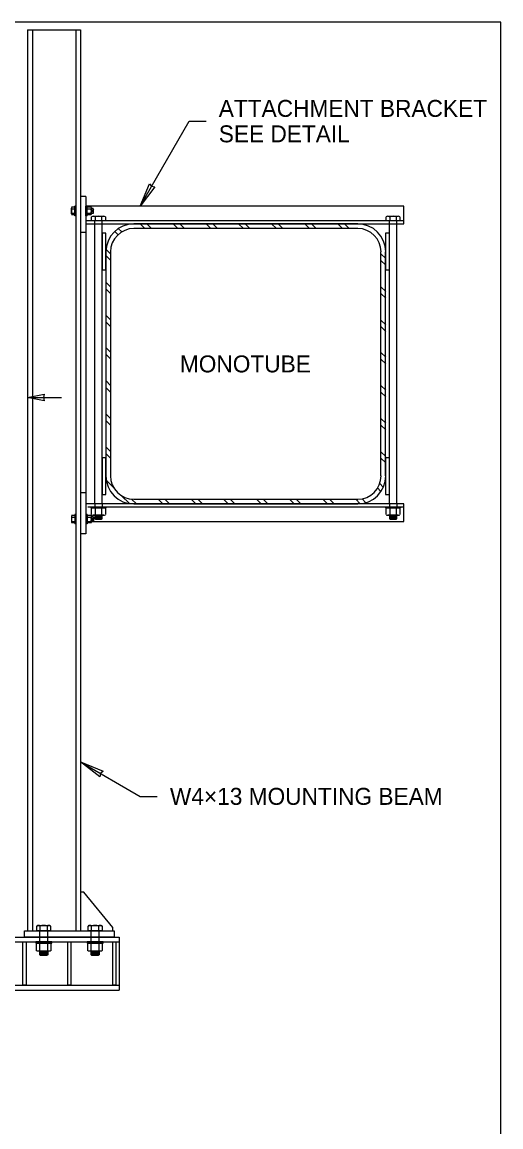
# Model space of a CAD drawing. Extents: x 99862 to 103151, y 100000 to 108076.
# Drawn here: x 102699 to 103151, y 107033 to 108076 of the extents above; entities that cross this region are included whole.
import ezdxf

# ---------------------------------------------------------------- set-up
doc = ezdxf.new("R2010")
doc.units = 0
for name, color, linetype in [('Level 1', 7, 'Continuous'), ('Level 13', 7, 'Continuous'), ('Level 15', 7, 'Continuous'), ('Level 2', 7, 'Continuous'), ('Level 20', 7, 'Continuous'), ('Level 3', 7, 'Continuous'), ('Level 30', 7, 'Continuous'), ('Level 36', 7, 'Continuous'), ('Level 4', 7, 'Continuous'), ('Level 60', 7, 'Continuous')]:
    doc.layers.add(name, color=color, linetype=linetype)

msp = doc.modelspace()

# ---------------------------------------------------------------- linework, layer by layer
at = {"layer": 'Level 1'}
msp.add_lwpolyline([(99862, 105999.5), (103151, 105999.5), (103151, 108075.5), (99862, 108075.5)], close=True, dxfattribs=at)
at = {"layer": 'Level 13'}
for p, q in [((102757.3, 107254.8), (102754.3, 107254.8)), ((102754.3, 107254.8), (102754.3, 107218.5)), ((102784.6, 107221.5), (102757.3, 107254.8)), ((102784.6, 107218.5), (102784.6, 107221.5)), ((102754.3, 107218.5), (102784.6, 107218.5)), ((102790.7, 107212.4), (102790.7, 107162.4))]:
    msp.add_line(p, q, dxfattribs=at)
msp.add_lwpolyline([(102701.3, 107218.5), (102786.1, 107218.5), (102786.1, 107212.4), (102701.3, 107212.4)], close=True, dxfattribs=at)
at = {"layer": 'Level 15'}
for p, q in [((102810.4, 107901.9), (102856.7, 107982.1)), ((102856.7, 107982.1), (102872.7, 107982.1)), ((102704.3, 107721.5), (102736.3, 107721.5)), ((102754.3, 107377.7), (102810.6, 107345.2)), ((102810.6, 107345.2), (102826.6, 107345.2))]:
    msp.add_line(p, q, dxfattribs=at)
for points in [[(102810.4, 107901.9), (102819.2, 107923.1), (102821.3, 107920.7), (102824.4, 107920.1)], [(102704.3, 107721.5), (102720, 107724.6), (102719.3, 107721.5), (102720, 107718.4)], [(102754.3, 107377.7), (102775.6, 107368.9), (102773.2, 107366.8), (102772.6, 107363.7)]]:
    msp.add_lwpolyline(points, close=True, dxfattribs=at)
at = {"layer": 'Level 2'}
for p, q in [((102704.3, 108068.3), (102754.3, 108068.3)), ((102704.3, 108068.3), (102704.3, 107218.5)), ((102087.3, 107212.4), (102790.7, 107212.4))]:
    msp.add_line(p, q, dxfattribs=at)
at = {"layer": 'Level 3'}
for p, q in [((102759.3, 107901.9), (102759.3, 107604.4)), ((103059.3, 107888.1), (102759.3, 107888.1)), ((102764.6, 107888.1), (102764.6, 107891.8)), ((102766.3, 107892.3), (102776.1, 107892.3)), ((102767.7, 107885.2), (102767.7, 107888.1)), ((102767.9, 107891.8), (102767.9, 107888.1)), ((102774.4, 107888.1), (102774.4, 107891.8)), ((102774.6, 107885.2), (102774.6, 107888.1)), ((102777.7, 107891.8), (102777.7, 107888.1)), ((103042.7, 107888.1), (103042.7, 107891.8)), ((103044.3, 107892.3), (103054.1, 107892.3)), ((103045.7, 107885.2), (103045.7, 107888.1)), ((103046, 107891.8), (103046, 107888.1)), ((103052.5, 107888.1), (103052.5, 107891.8)), ((103052.7, 107885.2), (103052.7, 107888.1)), ((103055.7, 107891.8), (103055.7, 107888.1)), ((102767.7, 107621.1), (102767.7, 107885.2)), ((102774.6, 107621.1), (102774.6, 107885.2)), ((102789.6, 107874.9), (102786.5, 107878)), ((102789.9, 107880.8), (102793.1, 107877.6)), ((103015.8, 107885.2), (102804.6, 107885.2)), ((103015.8, 107880.8), (102804.6, 107880.8)), ((102810.5, 107885.2), (102814.9, 107880.8)), ((102821.2, 107880.8), (102816.7, 107885.2)), ((102846.1, 107880.8), (102841.7, 107885.2)), ((102848, 107885.2), (102852.4, 107880.8)), ((102872.9, 107885.2), (102877.3, 107880.8)), ((102883.6, 107880.8), (102879.2, 107885.2)), ((102907.9, 107880.8), (102903.4, 107885.2)), ((102909.7, 107885.2), (102914.1, 107880.8)), ((102934.6, 107885.2), (102939.1, 107880.8)), ((102945.3, 107880.8), (102940.9, 107885.2)), ((102970.3, 107880.8), (102965.9, 107885.2)), ((102972.1, 107885.2), (102976.5, 107880.8)), ((102997.1, 107885.2), (103001.5, 107880.8)), ((103007.7, 107880.8), (103003.3, 107885.2)), ((103045.7, 107621.1), (103045.7, 107885.2)), ((103052.7, 107621.1), (103052.7, 107885.2)), ((102778.1, 107858.7), (102778.1, 107647.5)), ((102778.1, 107855.2), (102782.5, 107850.8)), ((102782.5, 107857), (102778.2, 107861.3)), ((102782.5, 107858.7), (102782.5, 107647.5)), ((103037.8, 107647.5), (103037.8, 107858.7)), ((103037.8, 107856.9), (103042.3, 107852.5)), ((103042.2, 107647.5), (103042.2, 107858.7)), ((103042.3, 107846.3), (103037.8, 107850.7)), ((102778.1, 107830.2), (102782.5, 107825.8)), ((102782.5, 107819.5), (102778.1, 107823.9)), ((103042.3, 107821.3), (103037.8, 107825.7)), ((103037.8, 107819.5), (103042.3, 107815)), ((102782.5, 107794.6), (102778.1, 107799)), ((102778.1, 107792.7), (102782.5, 107788.3)), ((103037.8, 107794.5), (103042.3, 107790.1)), ((103042.3, 107783.8), (103037.8, 107788.3)), ((102778.1, 107768.5), (102782.5, 107764.1)), ((102782.5, 107757.8), (102778.1, 107762.2)), ((103042.3, 107759.6), (103037.8, 107764)), ((103037.8, 107757.7), (103042.3, 107753.3)), ((102782.5, 107732.8), (102778.1, 107737.3)), ((102778.1, 107731), (102782.5, 107726.6)), ((103037.8, 107732.8), (103042.3, 107728.3)), ((103042.3, 107722.1), (103037.8, 107726.5)), ((102778.1, 107706), (102782.5, 107701.6)), ((102782.5, 107695.4), (102778.1, 107699.8)), ((103042.3, 107697.1), (103037.8, 107701.5)), ((103037.8, 107695.3), (103042.3, 107690.9)), ((102782.5, 107670.4), (102778.1, 107674.8)), ((102778.1, 107668.6), (102782.5, 107664.2)), ((103037.8, 107670.3), (103042.3, 107665.9)), ((103042.3, 107659.7), (103037.8, 107664.1)), ((102778.5, 107643.3), (102785.9, 107635.8)), ((103034.6, 107636.1), (103037.8, 107632.9)), ((103040, 107636.9), (103036.6, 107640.3)), ((102792.9, 107628.8), (102800.3, 107621.4)), ((102806.9, 107621.1), (102802.4, 107625.6)), ((102804.6, 107625.5), (103015.8, 107625.5)), ((102831.9, 107621.1), (102827.5, 107625.5)), ((102833.7, 107625.5), (102838.1, 107621.1)), ((102858.7, 107625.5), (102863.1, 107621.1)), ((102869.3, 107621.1), (102864.9, 107625.5)), ((102893.6, 107621.1), (102889.2, 107625.5)), ((102895.4, 107625.5), (102899.9, 107621.1)), ((102920.4, 107625.5), (102924.8, 107621.1)), ((102931.1, 107621.1), (102926.7, 107625.5)), ((102956, 107621.1), (102951.6, 107625.5)), ((102957.9, 107625.5), (102962.3, 107621.1)), ((102982.8, 107625.5), (102987.3, 107621.1)), ((102993.5, 107621.1), (102989.1, 107625.5)), ((103018.3, 107621.2), (103014, 107625.5)), ((103019.9, 107625.9), (103023.5, 107622.2)), ((102761, 107618.2), (103059.3, 107618.2)), ((102767.7, 107621.1), (102767.7, 107618.2)), ((102767.9, 107617.2), (102767.9, 107610.9)), ((102774.4, 107610.9), (102774.4, 107617.2)), ((102774.6, 107621.1), (102774.6, 107618.2)), ((102804.6, 107621.1), (103015.8, 107621.1)), ((103045.7, 107621.1), (103045.7, 107618.2)), ((103046, 107617.2), (103046, 107610.9)), ((103052.5, 107610.9), (103052.5, 107617.2)), ((103052.7, 107621.1), (103052.7, 107618.2)), ((102776.1, 107610.4), (102766.3, 107610.4)), ((102774.6, 107609.8), (102767.7, 107609.8)), ((102774.6, 107608.4), (102767.7, 107608.4)), ((102767.7, 107607.1), (102774.6, 107607.1)), ((102774, 107609.1), (102768.3, 107609.1)), ((102774, 107607.8), (102768.3, 107607.8)), ((103054.1, 107610.4), (103044.3, 107610.4)), ((103052.7, 107609.8), (103045.7, 107609.8)), ((103052.7, 107608.4), (103045.7, 107608.4)), ((103045.7, 107607.1), (103052.7, 107607.1)), ((103052, 107609.1), (103046.4, 107609.1)), ((103052, 107607.8), (103046.4, 107607.8))]:
    msp.add_line(p, q, dxfattribs=at)
for points in [[(102759.3, 107885.2), (103059.3, 107885.2), (103059.3, 107901.9), (102759.3, 107901.9)], [(102759.3, 107604.4), (103059.3, 107604.4), (103059.3, 107621.1), (102759.3, 107621.1)], [(102778.1, 107618.2), (102778.1, 107617.2), (102764.2, 107617.2), (102764.2, 107618.2)], [(102764.6, 107610.9), (102764.6, 107617.2), (102777.7, 107617.2), (102777.7, 107610.9)], [(103056.2, 107618.2), (103056.2, 107617.2), (103042.3, 107617.2), (103042.3, 107618.2)], [(103042.7, 107610.9), (103042.7, 107617.2), (103055.7, 107617.2), (103055.7, 107610.9)], [(102767.7, 107610.4), (102767.7, 107607.1), (102768.3, 107606.5), (102774, 107606.5), (102774.6, 107607.1), (102774.6, 107610.4)], [(103045.7, 107610.4), (103045.7, 107607.1), (103046.4, 107606.5), (103052, 107606.5), (103052.7, 107607.1), (103052.7, 107610.4)]]:
    msp.add_lwpolyline(points, dxfattribs=at)
for points in [[(102778.1, 107876.5), (102774.6, 107876.5), (102774.6, 107841.8), (102778.1, 107841.8)], [(103042.2, 107841.8), (103045.7, 107841.8), (103045.7, 107876.5), (103042.2, 107876.5)], [(102778.1, 107664.5), (102774.6, 107664.5), (102774.6, 107629.8), (102778.1, 107629.8)], [(103042.2, 107629.8), (103045.7, 107629.8), (103045.7, 107664.5), (103042.2, 107664.5)]]:
    msp.add_lwpolyline(points, close=True, dxfattribs=at)
for centre, radius, start, end in [((102766.3, 107889.5), 2.82, 54.7356, 125.2644), ((102771.2, 107881), 11.3, 73.2213, 106.7787), ((102776.1, 107889.5), 2.82, 54.7356, 125.2644), ((103044.3, 107889.5), 2.82, 54.7356, 125.2644), ((103049.2, 107881), 11.3, 73.2213, 106.7787), ((103054.1, 107889.5), 2.82, 54.7356, 125.2644), ((102804.6, 107858.7), 26.5, 90, 180), ((102804.6, 107858.7), 22.1, 90, 180), ((103015.8, 107858.7), 26.5, 360, 90), ((103015.8, 107858.7), 22.1, 360, 90), ((102804.6, 107647.5), 26.5, 180, 270), ((102804.6, 107647.5), 22.1, 180, 270), ((103015.8, 107647.5), 26.5, 270, 0), ((103015.8, 107647.5), 22.1, 270, 0), ((102766.3, 107613.2), 2.82, 234.7356, 305.2644), ((102771.2, 107621.7), 11.3, 253.2213, 286.7787), ((102776.1, 107613.2), 2.82, 234.7356, 305.2644), ((103044.3, 107613.2), 2.82, 234.7356, 305.2644), ((103049.2, 107621.7), 11.3, 253.2213, 286.7787), ((103054.1, 107613.2), 2.82, 234.7356, 305.2644)]:
    msp.add_arc(centre, radius, start, end, dxfattribs=at)
at = {"layer": 'Level 30'}
for p, q in [((102716.2, 107218.5), (102716.2, 107222.9)), ((102722.7, 107222.9), (102722.7, 107218.5)), ((102764.7, 107218.5), (102764.7, 107222.9)), ((102771.2, 107222.9), (102771.2, 107218.5)), ((102714.1, 107199.4), (102724.8, 107199.4)), ((102715.7, 107198.7), (102723.3, 107198.7)), ((102715.9, 107199.9), (102715.9, 107206.8)), ((102716.4, 107198), (102722.5, 107198)), ((102723, 107206.8), (102723, 107199.9)), ((102762.6, 107199.4), (102773.3, 107199.4)), ((102764.2, 107198.7), (102771.7, 107198.7)), ((102764.4, 107199.9), (102764.4, 107206.8)), ((102764.9, 107198), (102771, 107198)), ((102771.5, 107206.8), (102771.5, 107199.9)), ((102715.7, 107197.2), (102723.3, 107197.2)), ((102723.3, 107195.8), (102715.7, 107195.8)), ((102716.4, 107196.5), (102722.5, 107196.5)), ((102764.2, 107197.2), (102771.7, 107197.2)), ((102771.7, 107195.8), (102764.2, 107195.8)), ((102764.9, 107196.5), (102771, 107196.5))]:
    msp.add_line(p, q, dxfattribs=at)
for points in [[(102725.1, 107223.4), (102726, 107222.9), (102726, 107218.5), (102712.9, 107218.5), (102712.9, 107222.9), (102713.8, 107223.4), (102725.1, 107223.4)], [(102773.6, 107223.4), (102774.5, 107222.9), (102774.5, 107218.5), (102761.4, 107218.5), (102761.4, 107222.9), (102762.3, 107223.4), (102773.6, 107223.4)], [(102711.9, 107207.9), (102711.9, 107206.8), (102727, 107206.8), (102727, 107207.9), (102711.9, 107207.9)], [(102726.6, 107199.9), (102726.6, 107206.8), (102712.4, 107206.8), (102712.4, 107199.9)], [(102723.3, 107199.4), (102723.3, 107195.8), (102722.5, 107195.1), (102716.4, 107195.1), (102715.7, 107195.8), (102715.7, 107199.4)], [(102760.4, 107207.9), (102760.4, 107206.8), (102775.5, 107206.8), (102775.5, 107207.9), (102760.4, 107207.9)], [(102775.1, 107199.9), (102775.1, 107206.8), (102760.8, 107206.8), (102760.8, 107199.9)], [(102771.7, 107199.4), (102771.7, 107195.8), (102771, 107195.1), (102764.9, 107195.1), (102764.2, 107195.8), (102764.2, 107199.4)]]:
    msp.add_lwpolyline(points, dxfattribs=at)
for centre, radius, start, end in [((102714.5, 107220.7), 2.78, 52.8251, 125.1741), ((102719.5, 107213.6), 9.81, 70.4632, 109.5368), ((102724.4, 107220.7), 2.78, 54.8259, 127.1749), ((102763, 107220.7), 2.78, 52.8251, 125.1741), ((102768, 107213.6), 9.81, 70.4632, 109.5368), ((102772.9, 107220.7), 2.78, 54.8259, 127.1749), ((102714.1, 107202.5), 3.08, 234.7356, 305.2644), ((102719.5, 107211.7), 12.3, 253.2213, 286.7787), ((102724.8, 107202.5), 3.08, 234.7356, 305.2644), ((102762.6, 107202.5), 3.08, 234.7356, 305.2644), ((102768, 107211.7), 12.3, 253.2213, 286.7787), ((102773.3, 107202.5), 3.08, 234.7356, 305.2644)]:
    msp.add_arc(centre, radius, start, end, dxfattribs=at)
at = {"layer": 'Level 36'}
for p, q in [((102715.7, 107207.9), (102715.7, 107218.5)), ((102723.3, 107207.9), (102723.3, 107218.5)), ((102764.2, 107207.9), (102764.2, 107218.5)), ((102771.7, 107207.9), (102771.7, 107218.5))]:
    msp.add_line(p, q, dxfattribs=at)
at = {"layer": 'Level 4'}
for p, q in [((102708.9, 108068.3), (102708.9, 107218.5)), ((102749.8, 108068.3), (102749.8, 107218.5)), ((102754.3, 108068.3), (102754.3, 107218.5)), ((102759.3, 107911), (102754.3, 107911)), ((102759.3, 107911), (102759.3, 107901.9)), ((102745.6, 107894.6), (102745.6, 107900.1)), ((102748.7, 107900.8), (102745.8, 107900.8)), ((102745.8, 107899.3), (102748.7, 107899.3)), ((102748.7, 107892.9), (102748.7, 107901.9)), ((102749.8, 107901.9), (102748.7, 107901.9)), ((102748.7, 107893.8), (102748.7, 107900.8)), ((102760.4, 107901.9), (102759.3, 107901.9)), ((102759.3, 107892.9), (102759.3, 107901.9)), ((102760.4, 107892.9), (102760.4, 107901.9)), ((102760.4, 107893.8), (102760.4, 107900.8)), ((102764.2, 107900.8), (102760.4, 107900.8)), ((102760.4, 107899.3), (102764.2, 107899.3)), ((102764.5, 107894.6), (102764.5, 107900.1)), ((102766.3, 107899.6), (102764.5, 107899.6)), ((102765.5, 107896.1), (102765.5, 107898.6)), ((102766.3, 107899.6), (102766.5, 107899.2)), ((102766.5, 107895.5), (102766.5, 107899.2)), ((102745.8, 107895.3), (102748.7, 107895.3)), ((102748.7, 107893.8), (102745.8, 107893.8)), ((102749.8, 107892.9), (102748.7, 107892.9)), ((102760.4, 107892.9), (102759.3, 107892.9)), ((102760.4, 107895.3), (102764.2, 107895.3)), ((102764.2, 107893.8), (102760.4, 107893.8)), ((102766.3, 107895), (102764.5, 107895)), ((102766.3, 107895), (102766.5, 107895.5)), ((102759.3, 107876.9), (102754.3, 107876.9)), ((102759.3, 107631.4), (102754.3, 107631.4)), ((102745.6, 107609.4), (102745.6, 107603.9)), ((102748.7, 107610.1), (102745.8, 107610.1)), ((102745.8, 107608.6), (102748.7, 107608.6)), ((102745.8, 107604.6), (102748.7, 107604.6)), ((102748.7, 107611), (102748.7, 107602.1)), ((102749.8, 107611), (102748.7, 107611)), ((102748.7, 107610.1), (102748.7, 107603.1)), ((102760.4, 107611), (102759.3, 107611)), ((102759.3, 107611), (102759.3, 107602.1)), ((102759.3, 107604.4), (102759.3, 107592.9)), ((102760.4, 107611), (102760.4, 107602.1)), ((102760.4, 107610.1), (102760.4, 107603.1)), ((102764.2, 107610.1), (102760.4, 107610.1)), ((102760.4, 107608.6), (102764.2, 107608.6)), ((102760.4, 107604.6), (102764.2, 107604.6)), ((102764.5, 107609.4), (102764.5, 107603.9)), ((102766.3, 107608.9), (102764.5, 107608.9)), ((102765.5, 107607.9), (102765.5, 107605.4)), ((102766.3, 107608.9), (102766.5, 107608.5)), ((102766.3, 107604.3), (102766.5, 107604.8)), ((102766.5, 107608.5), (102766.5, 107604.8)), ((102748.7, 107603.1), (102745.8, 107603.1)), ((102749.8, 107602.1), (102748.7, 107602.1)), ((102760.4, 107602.1), (102759.3, 107602.1)), ((102764.2, 107603.1), (102760.4, 107603.1)), ((102766.3, 107604.3), (102764.5, 107604.3)), ((102759.3, 107592.9), (102754.3, 107592.9)), ((102673.3, 107207.9), (102790.7, 107207.9)), ((102673.3, 107167), (102790.7, 107167)), ((102087.3, 107162.4), (102790.7, 107162.4))]:
    msp.add_line(p, q, dxfattribs=at)
for points in [[(102699.8, 107207.9), (102702.8, 107207.9), (102702.8, 107167), (102699.8, 107167)], [(102742.2, 107207.9), (102745.2, 107207.9), (102745.2, 107167), (102742.2, 107167)], [(102784.6, 107207.9), (102787.7, 107207.9), (102787.7, 107167), (102784.6, 107167)]]:
    msp.add_lwpolyline(points, close=True, dxfattribs=at)
for centre, radius, start, end in [((102746.9, 107900.1), 1.27, 144.7199, 215.2801), ((102754.4, 107897.3), 8.76, 166.7504, 193.2496), ((102763.2, 107900.1), 1.27, 324.7199, 35.2801), ((102755.7, 107897.3), 8.76, 346.7504, 13.2496), ((102746.9, 107894.6), 1.27, 144.7199, 215.2801), ((102763.2, 107894.6), 1.27, 324.7199, 35.2801), ((102746.9, 107609.4), 1.27, 144.7199, 215.2801), ((102754.4, 107606.6), 8.76, 166.7504, 193.2496), ((102746.9, 107603.9), 1.27, 144.7199, 215.2801), ((102763.2, 107609.4), 1.27, 324.7199, 35.2801), ((102755.7, 107606.6), 8.76, 346.7504, 13.2496), ((102763.2, 107603.9), 1.27, 324.7199, 35.2801)]:
    msp.add_arc(centre, radius, start, end, dxfattribs=at)
at = {"layer": 'Level 60'}
msp.add_line((103151, 108075.5), (103151, 108075.5), dxfattribs=at)

# ---------------------------------------------------------------- texts
at = {"layer": 'Level 20'}
for s, p in [('ATTACHMENT BRACKET', (102884.7, 107986.1)), ('SEE DETAIL', (102884.7, 107962.1)), ('MONOTUBE', (102848, 107745.1)), ('W4×13 MOUNTING BEAM', (102838.6, 107337.2))]:
    msp.add_text(s, height=16, dxfattribs=at).set_placement(p)

doc.saveas('drawing.dxf')
